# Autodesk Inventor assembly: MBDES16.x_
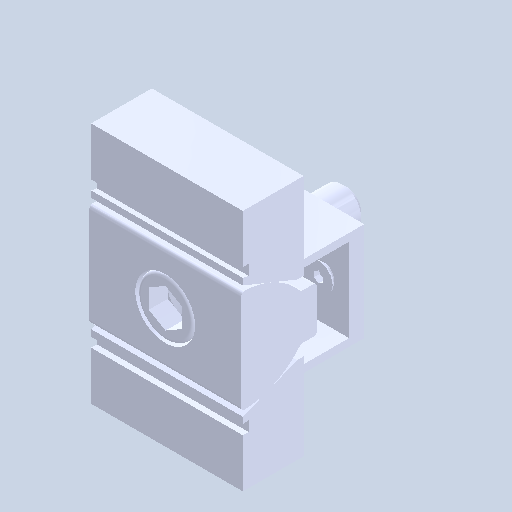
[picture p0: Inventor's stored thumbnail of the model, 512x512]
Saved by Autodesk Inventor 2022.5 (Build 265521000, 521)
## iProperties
Created: 2024-02
Part Number: MBDES16.x_
Document SubType Name: Assembly
Designer: ImaoCorp
Author: ImaoCorp
Sending System: SOLIDWORKS 2022-2022290
MC: AMD64
MC_MODEL: Intel64 Family 6 Model 60 Stepping 3, GenuineIntel
OS: Windows_NT
FRU: Parasolid Version 33.1, build 260,  4-25-2022
FORMAT: text
GUISE: transmit
KEY: FILEMBDES16.x_t
DATE: Wed Feb 14 09:59:39 2024
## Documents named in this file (6)
- Y:\5.更新分\2024年対応\0209_MBDES\mbdes16\MBDES16.x_.iam
- Y:\5.更新分\2024年対応\0209_MBDES\mbdes16\MBDES16_01.ipt
- Y:\5.更新分\2024年対応\0209_MBDES\mbdes16\MBDES16_02.ipt
- Y:\5.更新分\2024年対応\0209_MBDES\mbdes16\MBDES16_03.ipt
- Y:\5.更新分\2024年対応\0209_MBDES\mbdes16\MBDES16_04.ipt
- Y:\5.更新分\2024年対応\0209_MBDES\mbdes16\MBDES16_05.ipt
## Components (5 placed, 5 different names)
1. MBDES16_01
2. MBDES16_02
3. MBDES16_03
4. MBDES16_04
5. MBDES16_05
